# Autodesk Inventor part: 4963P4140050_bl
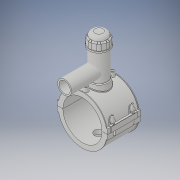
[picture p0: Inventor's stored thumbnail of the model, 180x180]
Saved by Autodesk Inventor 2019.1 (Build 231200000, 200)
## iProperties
Created: 2017-07
Part Number: 4963P4140050_bl
Material: Generic
Document SubType Name: Modeling
Designer: KIM
Density: 1 g/cm^3
Appearance: Default
Author: KIM
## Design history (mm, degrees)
derived "4963P4.ipt"
feature "Solid1::4963P4.ipt" dims "ScaleForDerivedMember" = 10
feature "Solid2::4963P4.ipt" dims "ScaleForDerivedMember" = 10
feature "Solid3::4963P4.ipt" dims "ScaleForDerivedMember" = 10
tag "TaggingFeature1"
body "Solid1"
body "Solid2"
body "Solid3"
other parameters: "d3" = 35 [user parameter], "d4" = 118 [user parameter], "d5" = 0 [user parameter], "d6" = 0.1 [user parameter], "d8" = 0 [user parameter], "d19" = 6 [user parameter], "d20" = 6 [user parameter], "d21" = 70.8 [user parameter], "d23" = 0 [user parameter], "d24" = 35.4 [user parameter], "d26" = 0 [user parameter], "d27" = 3 [user parameter], "d28" = 3 [user parameter], "d29" = 3 [user parameter], "d30" = 46.66667 [user parameter], "d31" = 6 [user parameter], "d32" = 0 [user parameter], "d33" = 0 [user parameter], "d34" = 0.6 [user parameter], "d40" = 88.816 [user parameter], "d43" = 0 [user parameter], "d45" = 0 [user parameter], "d47" = 156.2 [user parameter], "d70" = 15 [user parameter], "d72" = 0 [user parameter], "d73" = 6 [user parameter], "d75" = 5 [user parameter], "d76" = 0 [user parameter], "d77" = 7 [user parameter], "d79" = 15 [user parameter], "d80" = 47.2 [user parameter], "d82" = 5 deg [user parameter], "d84" = 4 [user parameter], "d85" = 14 [user parameter], "d86" = 0 [user parameter], "d87" = 3 [user parameter], "d88" = 0 [user parameter], "d89" = 1 [user parameter], "d90" = 1 [user parameter], "d91" = 94.4 [user parameter], "d92" = 0 [user parameter], "d93" = 0.5 [user parameter], "d94" = 73.68421 [user parameter], "d96" = 174.216 [user parameter], "d97" = 2.36 [user parameter], "d98" = 0 [user parameter], "d102" = 1.4 [user parameter], "d120" = 140 deg [user parameter], "d121" = 24.228 [user parameter], "d122" = 20 deg [user parameter], "d123" = 341.6 [user parameter], "d124" = 102.48 [user parameter], "d126" = 0 [user parameter], "d143" = 144.2 [user parameter], "d145" = 23.69231 [user parameter], "d149" = 2.1 [user parameter], "d150" = 26.06154 [user parameter], "d153" = 118 [user parameter], "d154" = 0 [user parameter], "d156" = 85.4 [user parameter], "d157" = 160 deg [user parameter], "d159" = 6.16 [user parameter], "d161" = 2.1 [user parameter], "d162" = 70.8 [user parameter], "d163" = 0 [user parameter], "d167" = 14 [user parameter], "d168" = 83.31707 [user parameter], "d170" = 3.75 [user parameter], "d172" = 0 [user parameter], "d173" = 1 [user parameter], "d176" = 20 deg [user parameter], "d177" = 9.8 [user parameter], "d178" = 30.8 [user parameter], "d180" = 0 [user parameter], "d183" = 12.32 [user parameter], "d184" = 7.84 [user parameter], "d185" = 38.35 [user parameter], "d186" = 38.35 [user parameter], "d187" = 85.4 [user parameter], "d188" = 9.24 [user parameter], "d189" = 9.8 [user parameter], "d190" = 0 [user parameter], "d191" = 128.1 [user parameter], "d193" = 8 [user parameter], "d194" = 4.13 [user parameter], "d195" = 90 deg [user parameter], "d197" = 0 [user parameter], "d199" = 0 [user parameter], "d200" = 15.4 [user parameter], "d202" = 0 [user parameter], "d203" = 177 [user parameter], "d204" = 66.5 [user parameter], "d205" = 49 [user parameter], "d206" = 59.5 [user parameter], "d207" = 132.75 [user parameter], "d208" = 138.06 [user parameter], "d209" = 164.61 [user parameter], "d210" = 60.2 [user parameter], "d212" = 56 [user parameter], "d213" = 35.1 [user parameter], "d216" = 0 [user parameter], "d217" = 14 [user parameter], "d218" = 14 [user parameter], "d219" = 2.8 [user parameter], "d224" = 0 [user parameter], "d225" = 64 [user parameter], "d228" = 123 [user parameter], "d230" = 5.6 [user parameter], "L_" = 118 [user parameter], "d_t" = 6 [user parameter], "H_2" = 177 [user parameter], "H_1" = 64 [user parameter], "H_" = 123 [user parameter], "d1" = 170.8 [user parameter], "d148" = 2.1 [user parameter], "d160" = 2.1 [user parameter], "d169" = 3.75 [user parameter], "d192" = 8 [user parameter]
